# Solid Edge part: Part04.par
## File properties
Accuracy: 0.99
Author: Robert a Rhodes jr
Template: Normal.par
Last saved by: Rajat Kamboj
Revision: 7
Application: Solid Edge
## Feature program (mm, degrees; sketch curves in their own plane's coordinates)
body "unnamed Body 1"
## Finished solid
Body 1: solid body, 43 faces, 102 edges, 68 vertices.
  Faces by surface: cylinder 28, plane 15
  Edges by curve: circle 56, line 46
Bounding box of the edges (mm): 1353.852 x 457.200 x 1295.400, from (-676.9261, -203.2, -533.4) to (676.9261, 254, 762).
Cylindrical faces by radius (mm): R50.8 x6, R95.25 x6, R127 x5, R152.4 x2, R254 x2, R431.8 x2, R508 x2, R533.4 x3
Planar faces by outward normal: +x 1, +y 7, -x 1, -y 2, oblique 4
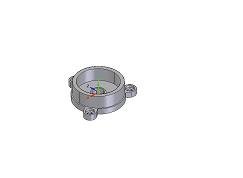
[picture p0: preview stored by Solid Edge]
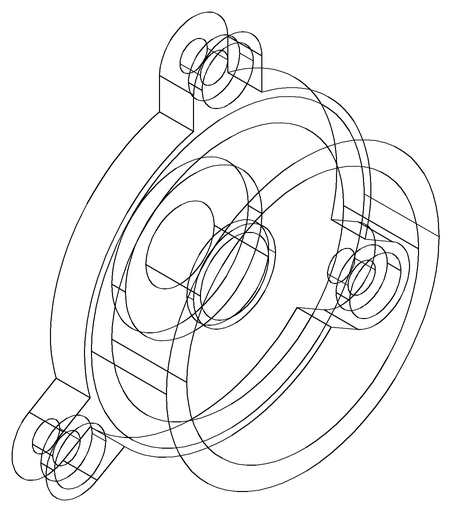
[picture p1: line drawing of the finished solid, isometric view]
